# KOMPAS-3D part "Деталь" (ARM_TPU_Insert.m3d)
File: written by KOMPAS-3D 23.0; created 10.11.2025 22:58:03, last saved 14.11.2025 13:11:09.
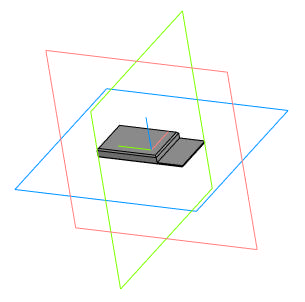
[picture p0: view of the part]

Document properties: Автор: ADMIN; Полное имя файла: D:\YandexDisk\Model\NVG\ARM mkII\ARM TPU Insert p2b.m3d

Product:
- Part/product: Деталь
    Масса: 0.003931

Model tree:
1. Эскиз:1
2. Элемент выдавливания:1
     Расстояние 1 = 2.3
3. Эскиз:2  (with: Элемент выдавливания:1)
4. Элемент выдавливания:2
     Расстояние 2 = 1.8
5. Фаска:1  (with: Элемент выдавливания:1)
     Угол = 45; Длина 1 = 0.4; Длина 2 = 0.4
6. Фаска:2  (with: Элемент выдавливания:1)
     Угол = 45; Длина 1 = 0.2; Длина 2 = 0.2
